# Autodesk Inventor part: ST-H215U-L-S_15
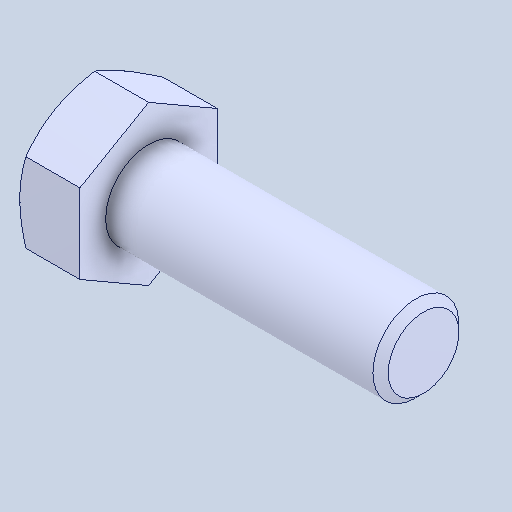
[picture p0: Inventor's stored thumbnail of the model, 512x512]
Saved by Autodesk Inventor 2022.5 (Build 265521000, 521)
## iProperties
Created: 2024-07
Part Number: ST-H215U-L-S_15
Material: 一般
Document SubType Name: Modeling
Designer: ImaoCorp
Density: 1 g/cm^3
Appearance: 既定
Author: ImaoCorp
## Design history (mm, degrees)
feature "ST-H215U-L-S_15"
node "ソリッド1"
